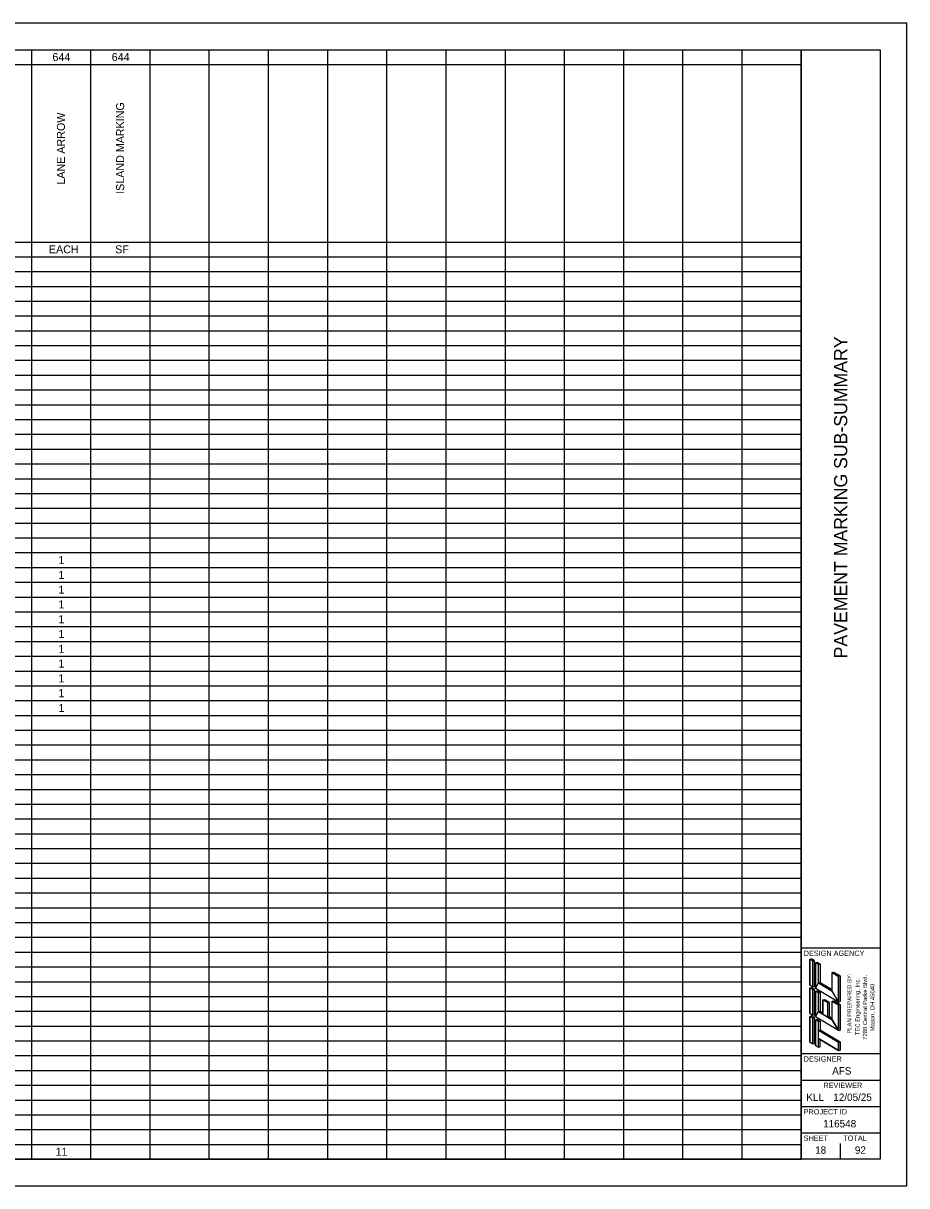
# Model space of a CAD drawing. Extents: x 0 to 34, y 0 to 22.
# Drawn here: x 17.29 to 34, y 0 to 22 of the extents above; entities that cross this region are included whole.
import ezdxf

# ---------------------------------------------------------------- set-up
doc = ezdxf.new("R2010")
doc.units = 0
for name, color, linetype in [('Default', 7, 'Continuous'), ('SH_Border', 7, 'Continuous'), ('SH_Cut_Line', 7, 'Continuous'), ('SH_Data', 7, 'Continuous'), ('SH_Text', 7, 'Continuous')]:
    doc.layers.add(name, color=color, linetype=linetype)

msp = doc.modelspace()

# ---------------------------------------------------------------- linework, layer by layer
at = {"layer": 'Default'}
for p, q in [((1.5, 21.5), (32, 21.5)), ((17.442, 21.5), (17.442, 0.502)), ((18.562, 21.5), (18.562, 0.502)), ((19.681, 21.5), (19.681, 0.502)), ((20.801, 21.5), (20.801, 0.502)), ((21.921, 21.5), (21.921, 0.502)), ((23.041, 21.5), (23.041, 0.502)), ((24.161, 21.5), (24.161, 0.502)), ((25.281, 21.5), (25.281, 0.502)), ((26.401, 21.5), (26.401, 0.502)), ((27.521, 21.5), (27.521, 0.502)), ((28.64, 21.5), (28.64, 0.502)), ((29.76, 21.5), (29.76, 0.502)), ((30.88, 21.5), (30.88, 0.502)), ((32, 21.5), (32, 0.502)), ((8.483, 21.22), (32, 21.22)), ((8.483, 17.86), (32, 17.86)), ((1.5, 17.58), (32, 17.58)), ((1.5, 17.3), (32, 17.3)), ((1.5, 17.021), (32, 17.021)), ((1.5, 16.741), (32, 16.741)), ((1.5, 16.461), (32, 16.461)), ((1.5, 16.181), (32, 16.181)), ((1.5, 15.901), (32, 15.901)), ((1.5, 15.621), (32, 15.621)), ((1.5, 15.341), (32, 15.341)), ((1.5, 15.061), (32, 15.061)), ((1.5, 14.781), (32, 14.781)), ((1.5, 14.501), (32, 14.501)), ((1.5, 14.221), (32, 14.221)), ((1.5, 13.941), (32, 13.941)), ((1.5, 13.661), (32, 13.661)), ((1.5, 13.381), (32, 13.381)), ((1.5, 13.101), (32, 13.101)), ((1.5, 12.821), (32, 12.821)), ((1.5, 12.541), (32, 12.541)), ((1.5, 12.261), (32, 12.261)), ((1.5, 11.981), (32, 11.981)), ((1.5, 11.701), (32, 11.701)), ((1.5, 11.421), (32, 11.421)), ((1.5, 11.141), (32, 11.141)), ((1.5, 10.861), (32, 10.861)), ((1.5, 10.581), (32, 10.581)), ((1.5, 10.301), (32, 10.301)), ((1.5, 10.021), (32, 10.021)), ((1.5, 9.741), (32, 9.741)), ((1.5, 9.461), (32, 9.461)), ((1.5, 9.181), (32, 9.181)), ((1.5, 8.901), (32, 8.901)), ((1.5, 8.621), (32, 8.621)), ((1.5, 8.342), (32, 8.342)), ((1.5, 8.062), (32, 8.062)), ((1.5, 7.782), (32, 7.782)), ((1.5, 7.502), (32, 7.502)), ((1.5, 7.222), (32, 7.222)), ((1.5, 6.942), (32, 6.942)), ((1.5, 6.662), (32, 6.662)), ((1.5, 6.382), (32, 6.382)), ((1.5, 6.102), (32, 6.102)), ((1.5, 5.822), (32, 5.822)), ((1.5, 5.542), (32, 5.542)), ((1.5, 5.262), (32, 5.262)), ((1.5, 4.982), (32, 4.982)), ((1.5, 4.702), (32, 4.702)), ((1.5, 4.422), (32, 4.422)), ((1.5, 4.142), (32, 4.142)), ((1.5, 3.862), (32, 3.862)), ((1.5, 3.582), (32, 3.582)), ((1.5, 3.302), (32, 3.302)), ((1.5, 3.022), (32, 3.022)), ((1.5, 2.742), (32, 2.742)), ((1.5, 2.462), (32, 2.462)), ((1.5, 2.182), (32, 2.182)), ((1.5, 1.902), (32, 1.902)), ((1.5, 1.622), (32, 1.622)), ((1.5, 1.342), (32, 1.342)), ((1.5, 1.062), (32, 1.062)), ((1.5, 0.782), (32, 0.782)), ((1.5, 0.502), (32, 0.502))]:
    msp.add_line(p, q, dxfattribs=at)
at = {"layer": 'SH_Border'}
for p, q in [((32, 0.5), (32, 21.5)), ((32, 4.5), (33.5, 4.5)), ((32, 2.5), (33.5, 2.5)), ((32, 2), (33.5, 2)), ((32, 1.5), (33.5, 1.5)), ((32, 1), (33.5, 1))]:
    msp.add_line(p, q, dxfattribs=at)
msp.add_lwpolyline([(1.5, 21.5), (33.5, 21.5), (33.5, 0.5), (1.5, 0.5)], close=True, dxfattribs=at)
at = {"layer": 'SH_Cut_Line'}
msp.add_lwpolyline([(0, 0), (34, 0), (34, 22), (0, 22)], close=True, dxfattribs=at)
at = {"layer": 'SH_Data'}
for p, q in [((32.75, 3.5), (32.75, 3.5)), ((32.375, 0.675), (32.375, 0.675)), ((32.75, 0.5), (32.75, 0.8))]:
    msp.add_line(p, q, dxfattribs=at)
at = {"layer": 'SH_Text'}
for p, q in [((32.169, 4.285), (32.201, 4.294)), ((32.169, 3.799), (32.169, 4.285)), ((32.223, 4.253), (32.169, 4.285)), ((32.255, 4.261), (32.201, 4.294)), ((32.223, 4.253), (32.255, 4.261)), ((32.223, 3.767), (32.223, 4.253)), ((32.255, 3.775), (32.255, 4.261)), ((32.277, 4.221), (32.309, 4.229)), ((32.331, 4.188), (32.277, 4.221)), ((32.277, 3.735), (32.277, 4.221)), ((32.309, 4.229), (32.363, 4.196)), ((32.331, 4.188), (32.363, 4.196)), ((32.331, 3.837), (32.331, 4.188)), ((32.363, 4.196), (32.363, 3.845)), ((32.587, 4.034), (32.62, 4.042)), ((32.587, 3.683), (32.587, 4.034)), ((32.709, 3.961), (32.587, 4.034)), ((32.62, 4.042), (32.741, 3.97)), ((32.709, 3.961), (32.741, 3.97)), ((32.709, 3.475), (32.709, 3.961)), ((32.741, 3.97), (32.741, 3.484)), ((32.223, 3.767), (32.169, 3.799)), ((32.169, 3.745), (32.201, 3.754)), ((32.169, 3.259), (32.169, 3.745)), ((32.223, 3.713), (32.169, 3.745)), ((32.255, 3.722), (32.201, 3.754)), ((32.223, 3.767), (32.255, 3.775)), ((32.331, 3.837), (32.363, 3.845)), ((32.587, 3.683), (32.331, 3.837)), ((32.363, 3.845), (32.587, 3.711)), ((32.223, 3.713), (32.255, 3.722)), ((32.223, 3.227), (32.223, 3.713)), ((32.255, 3.236), (32.255, 3.722)), ((32.709, 3.475), (32.277, 3.735)), ((32.277, 3.681), (32.309, 3.689)), ((32.277, 3.195), (32.277, 3.681)), ((32.331, 3.648), (32.277, 3.681)), ((32.309, 3.689), (32.363, 3.656)), ((32.331, 3.648), (32.363, 3.656)), ((32.331, 3.297), (32.331, 3.648)), ((32.363, 3.656), (32.363, 3.305)), ((32.415, 3.519), (32.448, 3.527)), ((32.448, 3.527), (32.535, 3.474)), ((32.331, 3.297), (32.363, 3.305)), ((32.363, 3.305), (32.415, 3.274)), ((32.415, 3.519), (32.415, 3.247)), ((32.415, 3.519), (32.503, 3.466)), ((32.503, 3.466), (32.535, 3.474)), ((32.503, 3.466), (32.503, 3.194)), ((32.535, 3.474), (32.535, 3.202)), ((32.587, 3.494), (32.62, 3.502)), ((32.587, 3.143), (32.587, 3.494)), ((32.709, 3.421), (32.587, 3.494)), ((32.62, 3.502), (32.741, 3.43)), ((32.709, 3.475), (32.741, 3.484)), ((32.709, 3.421), (32.741, 3.43)), ((32.709, 2.935), (32.709, 3.421)), ((32.741, 3.43), (32.741, 2.944)), ((32.223, 3.227), (32.169, 3.259)), ((32.169, 3.205), (32.201, 3.215)), ((32.169, 2.719), (32.169, 3.205)), ((32.223, 3.173), (32.169, 3.205)), ((32.255, 3.181), (32.201, 3.215)), ((32.222, 3.173), (32.255, 3.181)), ((32.223, 3.227), (32.255, 3.236)), ((32.223, 2.687), (32.223, 3.173)), ((32.255, 2.695), (32.255, 3.181)), ((32.709, 2.935), (32.277, 3.195)), ((32.277, 3.141), (32.309, 3.151)), ((32.331, 3.108), (32.277, 3.141)), ((32.277, 2.655), (32.277, 3.141)), ((32.309, 3.151), (32.363, 3.116)), ((32.415, 3.247), (32.331, 3.297)), ((32.331, 3.108), (32.363, 3.116)), ((32.331, 2.944), (32.331, 3.108)), ((32.363, 3.116), (32.363, 2.952)), ((32.503, 3.194), (32.535, 3.202)), ((32.587, 3.143), (32.503, 3.194)), ((32.535, 3.202), (32.587, 3.171)), ((32.331, 2.944), (32.363, 2.952)), ((32.331, 2.944), (32.709, 2.717)), ((32.363, 2.952), (32.741, 2.725)), ((32.709, 2.935), (32.741, 2.944)), ((32.223, 2.687), (32.169, 2.719)), ((32.223, 2.687), (32.255, 2.695)), ((32.331, 2.622), (32.277, 2.655)), ((32.331, 2.787), (32.709, 2.56)), ((32.331, 2.622), (32.331, 2.787)), ((32.363, 2.63), (32.363, 2.767)), ((32.709, 2.717), (32.741, 2.725)), ((32.709, 2.56), (32.709, 2.717)), ((32.741, 2.725), (32.741, 2.568)), ((32.331, 2.622), (32.363, 2.63)), ((32.709, 2.56), (32.741, 2.568))]:
    msp.add_line(p, q, dxfattribs=at)
for points in [[(32.169, 3.799), (32.223, 3.767), (32.223, 4.253), (32.169, 4.285)], [(32.277, 3.735), (32.331, 3.837), (32.331, 4.188), (32.277, 4.221)], [(32.709, 3.475), (32.587, 3.683), (32.587, 4.034), (32.709, 3.961)], [(32.169, 3.259), (32.223, 3.227), (32.223, 3.713), (32.169, 3.745)], [(32.277, 3.735), (32.331, 3.837), (32.587, 3.683), (32.709, 3.475)], [(32.277, 3.195), (32.331, 3.297), (32.331, 3.648), (32.277, 3.681)], [(32.415, 3.247), (32.415, 3.519), (32.503, 3.466), (32.503, 3.194)], [(32.709, 2.935), (32.587, 3.143), (32.587, 3.494), (32.709, 3.421)], [(32.169, 2.719), (32.223, 2.687), (32.223, 3.173), (32.169, 3.205)], [(32.277, 3.195), (32.331, 3.297), (32.587, 3.143), (32.709, 2.935)], [(32.277, 2.655), (32.331, 2.622), (32.331, 3.108), (32.277, 3.141)], [(32.331, 2.787), (32.331, 2.944), (32.709, 2.717), (32.709, 2.56)]]:
    msp.add_lwpolyline(points, close=True, dxfattribs=at)

# ---------------------------------------------------------------- texts
at = {"layer": 'Default'}
for s, height, p in [('644', 0.1515, (17.841, 21.284)), ('644', 0.1515, (18.961, 21.284)), ('EACH', 0.1515, (17.774, 17.645)), ('SF', 0.1515, (19.027, 17.645)), ('1', 0.152, (17.953, 11.765)), ('1', 0.152, (17.953, 11.485)), ('1', 0.152, (17.953, 11.205)), ('1', 0.152, (17.953, 10.925)), ('1', 0.152, (17.953, 10.645)), ('1', 0.152, (17.953, 10.366)), ('1', 0.152, (17.953, 10.086)), ('1', 0.152, (17.953, 9.806)), ('1', 0.152, (17.953, 9.526)), ('1', 0.152, (17.953, 9.246)), ('1', 0.152, (17.953, 8.966)), ('11', 0.1515, (17.899, 0.567))]:
    msp.add_text(s, height=height, dxfattribs=at).set_placement(p)
for s, height, p in [('ISLAND MARKING', 0.15151, (19.197, 18.772)), ('LANE ARROW', 0.1515, (18.077, 18.947)), ('PLAN PREPARED BY:', 0.08, (32.954, 2.88)), ('TEC Engineering, Inc.', 0.08, (33.11, 2.851)), ('7288 Central Parke Blvd.', 0.08, (33.25, 2.762)), ('Mason, OH 45040', 0.08, (33.39, 2.925))]:
    msp.add_text(s, height=height, rotation=90, dxfattribs=at).set_placement(p)
at = {"layer": 'SH_Data'}
msp.add_text('PAVEMENT MARKING SUB-SUMMARY', height=0.25, rotation=90, dxfattribs=at).set_placement((32.875, 9.981))
for s, height, p in [('DESIGN AGENCY', 0.1, (32.05, 4.35)), ('DESIGNER', 0.1, (32.05, 2.35)), ('AFS', 0.14, (32.59, 2.105)), ('REVIEWER', 0.1, (32.422, 1.85)), ('KLL', 0.14, (32.101, 1.605)), ('12/05/25', 0.14, (32.611, 1.605)), ('PROJECT ID', 0.1, (32.05, 1.35)), ('116548', 0.14, (32.419, 1.105)), ('SHEET', 0.1, (32.05, 0.85)), ('TOTAL', 0.1, (32.8, 0.85)), ('18', 0.14, (32.268, 0.605)), ('92', 0.14, (33.019, 0.605))]:
    msp.add_text(s, height=height, dxfattribs=at).set_placement(p)

doc.saveas('drawing.dxf')
